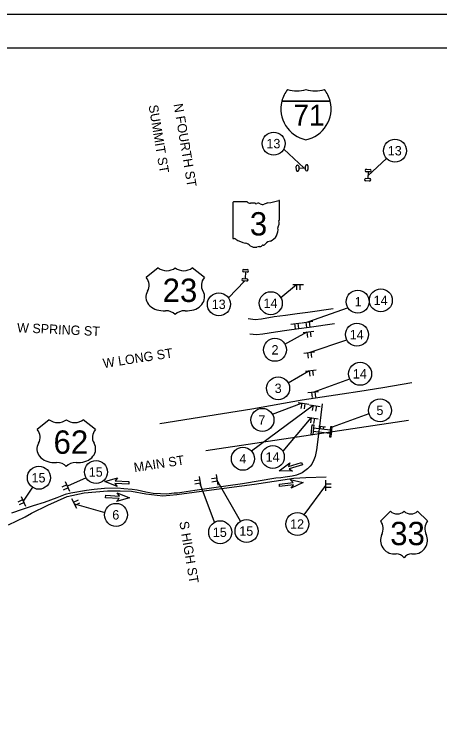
# Model space of a CAD drawing. Extents: x 0 to 680, y 0 to 440.
# Drawn here: x 417.5 to 544.5, y 225.4 to 440 of the extents above; entities that cross this region are included whole.
import ezdxf

# ---------------------------------------------------------------- set-up
doc = ezdxf.new("R2010")
doc.units = 0
for name, color, linetype in [('GM_X_Corporation_Text', 7, 'Continuous'), ('GM_X_County', 7, 'Continuous'), ('GM_X_County_Road_Text', 7, 'Continuous'), ('GM_X_Major_Lake', 7, 'Continuous'), ('GM_X_Major_River', 7, 'Continuous'), ('GM_X_Minor_Lake', 7, 'Continuous'), ('GM_X_Minor_River', 7, 'Continuous'), ('GM_X_Minor_River_Text', 7, 'Continuous'), ('GM_X_State_Location', 7, 'Continuous'), ('GM_X_Township_Text', 7, 'Continuous'), ('GM_X_Unincorporated_Location', 7, 'Continuous'), ('GM_X_Unincorporated_Text', 7, 'Continuous')]:
    doc.layers.add(name, color=color, linetype=linetype)

msp = doc.modelspace()

# ---------------------------------------------------------------- linework, layer by layer
at = {"layer": 'GM_X_Corporation_Text'}
for points in [[(509.45, 323.78), (508.34, 314.72), (507.7, 310.05), (507.29, 308.14), (506.94, 307.16), (506.33, 305.84), (505.8, 305.18), (505.05, 304.44), (503.41, 303.27), (501.78, 302.54), (500.42, 302.21), (498.4, 301.94), (497.08, 301.76), (495.57, 301.68), (485.62, 299.99), (476.34, 298.7), (471.42, 297.99), (466.21, 297.17), (465.2, 297.13), (462.96, 296.9), (461.12, 296.94), (458.95, 297.06), (456.78, 297.51), (454.16, 298.02), (452.7, 298.26), (450.19, 298.49), (448.34, 298.63), (444.42, 298.55), (441.36, 298.28), (439.1, 298), (434.38, 297.16), (432.71, 296.73), (430.18, 295.75), (426.46, 294.42), (423.12, 293.36), (419.85, 292.29), (416.65, 291.16)], [(415.79, 287.72), (420.78, 290.12), (422.67, 291.23), (427.47, 293.62), (433.31, 296.13), (438.41, 297.23), (445.33, 297.83), (449.12, 297.83), (452.53, 297.77), (456.75, 297.01), (461.88, 296.36), (466, 296.81), (476.41, 298.21), (489.2, 299.87), (500.99, 301.61), (504.58, 301.84), (510.59, 302.02)]]:
    msp.add_lwpolyline(points, dxfattribs=at)
at = {"layer": 'GM_X_County'}
msp.add_lwpolyline([(0, 0), (680, 0), (680, 440), (0, 440)], close=True, dxfattribs=at)
at = {"layer": 'GM_X_County_Road_Text'}
for p, q in [((460.49, 364.36), (456.86, 361.46)), ((474.27, 361.46), (470.64, 364.36)), ((461.94, 351.6), (462.66, 351.6)), ((468.47, 351.6), (469.19, 351.6)), ((427.96, 319.07), (424.33, 316.17)), ((441.73, 316.17), (438.11, 319.07)), ((429.41, 306.31), (430.13, 306.31)), ((435.93, 306.31), (436.66, 306.31)), ((529.8, 291.8), (526.9, 288.9)), ((540.82, 288.9), (537.92, 291.8)), ((530.96, 279.04), (531.54, 279.04)), ((536.18, 279.04), (536.76, 279.04))]:
    msp.add_line(p, q, dxfattribs=at)
for centre, radius, start, end in [((531.83, 293.87), 2.9, 225.573, 314.427), ((535.89, 293.87), 2.9, 225.573, 314.427), ((523.57, 286.57), 4.06, 334.5471, 35.0009), ((544.15, 286.57), 4.06, 144.9991, 205.4529), ((530.91, 283.1), 4.06, 154.8319, 270.6383), ((536.8, 283.1), 4.06, 269.3617, 25.1681), ((531.54, 276.14), 2.9, 36.8699, 90), ((536.18, 276.14), 2.9, 90, 143.1301)]:
    msp.add_arc(centre, radius, start, end, dxfattribs=at)
for centre, major_axis, start_param, end_param in [((463.03, 366.44), (-3.63, 0), 0.795399, 2.346194), ((468.1, 366.44), (-3.63, 0), 0.795399, 2.346194), ((452.71, 359.13), (5.08, 0), 5.838949, 6.894067), ((478.42, 359.13), (-5.08, 0), 5.672304, 6.727422), ((461.88, 355.66), (5.08, 0), 2.702327, 4.723529), ((469.25, 355.66), (-5.08, 0), 1.559657, 3.580859), ((462.66, 348.7), (-3.63, 0), 3.785094, 4.712389), ((468.47, 348.7), (-3.63, 0), 4.712389, 5.639684), ((430.5, 321.14), (-3.63, 0), 0.795399, 2.346194), ((435.57, 321.14), (-3.63, 0), 0.795399, 2.346194), ((420.17, 313.84), (5.08, 0), 5.838949, 6.894067), ((445.89, 313.84), (-5.08, 0), 5.672304, 6.727422), ((429.35, 310.37), (5.08, 0), 2.702327, 4.723529), ((436.72, 310.37), (-5.08, 0), 1.559657, 3.580859), ((430.13, 303.41), (-3.63, 0), 3.785094, 4.712389), ((435.93, 303.41), (-3.63, 0), 4.712389, 5.639684)]:
    msp.add_ellipse(centre, major_axis=major_axis, ratio=0.8, start_param=start_param, end_param=end_param, dxfattribs=at)
at = {"layer": 'GM_X_Major_Lake'}
for p, q in [((511.7, 315), (506.73, 315.55)), ((511.81, 315.99), (506.84, 316.55)), ((508.42, 317.13), (510.4, 316.91)), ((508.83, 316.33), (508.91, 317.07)), ((509.27, 315.77), (509.27, 315.77)), ((509.82, 316.22), (509.91, 316.96)), ((496.57, 303.87), (499.79, 306.2)), ((499.34, 305.1), (503.29, 306.29)), ((499.79, 306.2), (499.34, 305.1)), ((503.51, 305.57), (499.56, 304.38)), ((503.29, 306.29), (503.51, 305.57)), ((503.4, 305.93), (503.4, 305.93)), ((496.57, 303.87), (496.57, 303.87)), ((500.54, 303.71), (496.57, 303.87)), ((499.56, 304.38), (500.54, 303.71)), ((444.56, 300.6), (448.36, 301.72)), ((444.56, 300.6), (444.56, 300.6)), ((448.24, 299.12), (444.56, 300.6)), ((448.36, 301.72), (447.57, 300.83)), ((447.57, 300.83), (451.69, 300.64)), ((451.69, 300.64), (451.66, 299.89)), ((500.74, 300.36), (499.89, 301.2)), ((499.89, 301.2), (503.76, 300.33)), ((451.66, 299.89), (447.54, 300.08)), ((447.54, 300.08), (448.24, 299.12)), ((451.67, 300.26), (451.67, 300.26)), ((496.64, 299.9), (500.74, 300.36)), ((496.72, 299.15), (496.64, 299.9)), ((496.68, 299.52), (496.68, 299.52)), ((500.82, 299.62), (496.72, 299.15)), ((503.76, 300.33), (500.18, 298.61)), ((500.18, 298.61), (500.82, 299.62)), ((503.76, 300.33), (503.76, 300.33)), ((444.74, 295.79), (444.79, 296.54)), ((444.76, 296.17), (444.76, 296.17)), ((444.79, 296.54), (448.9, 296.31)), ((448.9, 296.31), (448.21, 297.28)), ((448.21, 297.28), (451.88, 295.77)), ((448.86, 295.56), (444.74, 295.79)), ((451.88, 295.77), (448.06, 294.68)), ((448.06, 294.68), (448.86, 295.56)), ((451.88, 295.77), (451.88, 295.77))]:
    msp.add_line(p, q, dxfattribs=at)
for points in [[(506.12, 314.62), (506.46, 317.6), (506.95, 317.54), (506.62, 314.56)], [(512.09, 313.95), (512.42, 316.93), (511.92, 316.99), (511.59, 314.01)]]:
    msp.add_lwpolyline(points, close=True, dxfattribs=at)
at = {"layer": 'GM_X_Major_River'}
for p, q in [((497.38, 414.1), (511.8, 414.1)), ((511.8, 414.1), (497.38, 414.1)), ((511.8, 414.1), (497.38, 414.1))]:
    msp.add_line(p, q, dxfattribs=at)
for centre, start, end in [((506.46, 411.8), 141.669, 165.8066), ((501.85, 426.58), 253.0091, 286.9909), ((507.33, 426.58), 253.0091, 286.9909), ((502.71, 411.8), 14.1934, 38.331), ((506.46, 411.8), 165.8066, 258.463), ((502.71, 411.8), 281.537, 14.1934)]:
    msp.add_arc(centre, 9.38, start, end, dxfattribs=at)
at = {"layer": 'GM_X_Minor_Lake'}
for p, q in [((497.95, 399.8), (503.9, 394.19)), ((523.07, 391.82), (528.61, 397.05)), ((481.42, 355.46), (486.27, 360.45)), ((497.08, 355.51), (501.75, 359.42)), ((517.15, 352.42), (505.02, 348.23)), ((498.27, 341.65), (504.96, 345.29)), ((505.55, 339.14), (516.78, 342.93)), ((499.25, 330.07), (505.4, 333.67)), ((506.75, 327.34), (517.67, 331.28)), ((494.62, 320.7), (503.22, 324.06)), ((488.28, 309.75), (506.73, 323.37)), ((512.5, 316.97), (523.41, 320.92)), ((497.73, 309.65), (506.16, 319.69)), ((438.94, 301.77), (433.34, 299.21)), ((485.06, 288.79), (478.01, 301.18)), ((422.93, 298.92), (420.2, 294.77)), ((477.31, 288.52), (473.04, 299.93)), ((504.07, 290.72), (510.51, 299.44)), ((435.43, 293.98), (444.55, 291.42))]:
    msp.add_line(p, q, dxfattribs=at)
for centre in [(494.94, 401.45), (531.16, 399.33), (478.59, 353.51), (494.08, 353.84), (520.03, 354.28), (526.93, 354.68), (519.8, 344.47), (495.33, 339.93), (520.74, 332.77), (496.27, 328.45), (526.69, 321.87), (491.58, 319.03), (494.69, 307.97), (485.75, 307.43), (441.92, 303.48), (424.85, 301.77), (447.88, 290.7), (502.01, 287.95), (478.97, 285.51), (486.85, 285.86)]:
    msp.add_circle(centre, 3.43, dxfattribs=at)
at = {"layer": 'GM_X_Minor_River_Text'}
msp.add_lwpolyline([(30, 430), (670, 430), (670, 10), (30, 10)], close=True, dxfattribs=at)
at = {"layer": 'GM_X_State_Location'}
msp.add_line((474.72, 309.85), (535.21, 318.98), dxfattribs=at)
at = {"layer": 'GM_X_Township_Text'}
for points in [[(512.66, 352.18), (505.13, 351.04), (501.98, 350.66), (498.46, 350.16), (495.04, 349.73), (491.27, 349.12), (489.38, 348.87), (487.37, 349.14)], [(513.09, 347.68), (505.56, 346.55), (502.41, 346.16), (498.89, 345.66), (495.46, 345.24), (491.7, 344.62), (489.8, 344.37), (487.8, 344.64)], [(536.19, 330.12), (527.57, 328.57), (520.64, 327.5), (515.41, 326.66), (503.46, 324.96), (488.41, 322.27), (475.33, 320.15), (460.98, 317.84)]]:
    msp.add_lwpolyline(points, dxfattribs=at)
at = {"layer": 'GM_X_Unincorporated_Location'}
for p, q in [((496.69, 378.78), (496.69, 384.3)), ((482.77, 383.86), (482.77, 373.29)), ((486.99, 384.04), (482.91, 384.04)), ((496.69, 378.78), (496.69, 378.78))]:
    msp.add_line(p, q, dxfattribs=at)
for centre, radius, start, end in [((491.73, 398.45), 14.76, 275.8445, 288.9065), ((496.54, 384.33), 0.155, 351.8621, 97.738), ((482.93, 383.88), 0.161, 98.1301, 188.1301), ((487.96, 385.27), 1.56, 231.6195, 271.1119), ((488.48, 378.11), 5.62, 80.4867, 94.9883), ((489.75, 383.94), 0.451, 219.7921, 297.1024), ((490.41, 382.72), 0.938, 54.4667, 119.1411), ((491.62, 384.39), 1.13, 233.8562, 294.8282), ((493.62, 380.81), 2.97, 97.3462, 120.7689), ((496.66, 378.37), 0.24, 107.944, 210.337), ((495.13, 377.67), 1.44, 340.033, 23.6496), ((496.53, 378.75), 0.166, 289.6038, 7.7341), ((492.56, 375.76), 3.69, 292.3089, 8.9858), ((497.25, 376.46), 1.05, 136.8065, 186.9296), ((482.93, 373.27), 0.163, 171.9584, 258.3066), ((482.96, 374.35), 1.24, 267.339, 280.6039), ((483.21, 372.68), 0.448, 29.7484, 93.2717), ((488.86, 382.18), 10.66, 240.4129, 257.1985), ((485.69, 368.55), 3.34, 47.1842, 75.836), ((491.56, 372.27), 1.19, 282.8732, 323.2771), ((494.12, 370.33), 2.02, 94.4031, 142.5768), ((489.29, 372.63), 2.12, 230.7004, 286.2918), ((490.52, 368.98), 1.74, 85.6951, 111.2099), ((490.67, 371.84), 1.13, 268.777, 315.5493), ((491.69, 370.82), 0.318, 65.7517, 132.6484)]:
    msp.add_arc(centre, radius, start, end, dxfattribs=at)
at = {"layer": 'GM_X_Unincorporated_Text'}
for p, q in [((501.74, 393.51), (501.7, 394.6)), ((502.45, 394.12), (504.43, 394.21)), ((504.45, 393.67), (504.41, 394.76)), ((522.62, 393.8), (523.7, 393.72)), ((523.15, 393.03), (523.01, 391.05)), ((522.47, 391.09), (523.56, 391.01)), ((485.98, 363.93), (487.07, 363.85)), ((486.51, 363.15), (486.38, 361.18)), ((485.83, 361.22), (486.92, 361.14)), ((500.64, 359.41), (503.84, 359.46)), ((501.76, 359.42), (501.79, 357.82)), ((502.24, 359.43), (502.24, 359.43)), ((502.72, 359.44), (502.75, 357.84)), ((500.08, 347.6), (503.25, 348.01)), ((501.19, 347.74), (501.4, 346.16)), ((501.67, 347.8), (501.67, 347.8)), ((502.14, 347.87), (502.35, 346.28)), ((503.43, 348.03), (506.6, 348.44)), ((504.54, 348.17), (504.75, 346.58)), ((505.02, 348.23), (505.02, 348.23)), ((505.49, 348.29), (505.7, 346.71)), ((503.74, 345.09), (506.92, 345.5)), ((504.85, 345.23), (505.06, 343.65)), ((505.33, 345.3), (505.33, 345.3)), ((505.81, 345.36), (506.01, 343.77)), ((503.96, 338.95), (507.14, 339.33)), ((505.08, 339.08), (505.27, 337.49)), ((505.55, 339.14), (505.55, 339.14)), ((506.03, 339.2), (506.22, 337.61)), ((504.46, 333.55), (507.63, 333.96)), ((505.57, 333.69), (505.77, 332.1)), ((506.04, 333.75), (506.04, 333.75)), ((506.52, 333.81), (506.72, 332.23)), ((505.17, 327.15), (508.34, 327.53)), ((506.28, 327.28), (506.47, 325.69)), ((506.75, 327.34), (506.75, 327.34)), ((507.23, 327.4), (507.42, 325.81)), ((502.23, 324.22), (505.39, 323.7)), ((503.33, 324.04), (503.07, 322.46)), ((503.81, 323.96), (503.81, 323.96)), ((504.28, 323.88), (504.02, 322.31)), ((505.62, 323.55), (508.78, 323.03)), ((506.73, 323.37), (506.47, 321.79)), ((507.2, 323.29), (507.2, 323.29)), ((507.68, 323.21), (507.41, 321.64)), ((505.06, 319.88), (508.22, 319.35)), ((506.16, 319.69), (505.9, 318.12)), ((506.64, 319.62), (506.64, 319.62)), ((507.11, 319.54), (506.85, 317.96)), ((477.76, 302.77), (478.25, 299.6)), ((432.65, 300.66), (434.03, 297.77)), ((472.87, 301.06), (471.29, 300.82)), ((472.7, 302.17), (473.18, 299.01)), ((472.94, 300.59), (472.94, 300.59)), ((477.94, 301.66), (476.35, 301.42)), ((478.08, 300.71), (476.5, 300.47)), ((478.01, 301.18), (478.01, 301.18)), ((510.54, 297.84), (510.47, 301.04)), ((433.14, 299.65), (431.69, 298.96)), ((433.55, 298.78), (432.11, 298.09)), ((433.34, 299.21), (433.34, 299.21)), ((473.01, 300.11), (471.43, 299.87)), ((510.5, 299.92), (512.1, 299.96)), ((510.51, 299.44), (510.51, 299.44)), ((510.52, 298.96), (512.12, 299)), ((419.51, 296.22), (420.89, 293.33)), ((419.99, 295.21), (418.55, 294.52)), ((420.41, 294.34), (418.96, 293.65)), ((420.2, 294.77), (420.2, 294.77)), ((436.13, 292.59), (434.72, 295.47)), ((435.21, 294.46), (436.65, 295.17)), ((435.42, 294.03), (435.42, 294.03)), ((435.63, 293.6), (437.07, 294.3))]:
    msp.add_line(p, q, dxfattribs=at)
for points in [[(505.14, 394.83), (505.18, 393.74)], [(502.43, 394.67), (502.47, 393.58)], [(523.69, 392.99), (522.61, 393.07)], [(523.54, 390.28), (522.46, 390.36)], [(487.06, 363.11), (485.97, 363.19)], [(486.91, 360.4), (485.82, 360.48)]]:
    msp.add_lwpolyline(points, dxfattribs=at)
for centre, start, end in [((502.07, 394.63), 6.2805, 184.6343), ((504.78, 394.79), 6.2805, 184.6343), ((502.11, 393.55), 186.2805, 4.6343), ((504.82, 393.71), 186.2805, 4.6343), ((522.62, 393.43), 89.8181, 268.1719), ((523.69, 393.35), 269.8181, 88.1719), ((522.47, 390.72), 89.8181, 268.1719), ((523.54, 390.64), 269.8181, 88.1719), ((485.98, 363.56), 89.8181, 268.1719), ((487.06, 363.48), 269.8181, 88.1719), ((485.83, 360.85), 89.8181, 268.1719), ((486.91, 360.77), 269.8181, 88.1719)]:
    msp.add_arc(centre, 0.367, start, end, dxfattribs=at)

# ---------------------------------------------------------------- texts
at = {"layer": 'GM_X_County_Road_Text'}
for s, p in [('23', (461.78, 354.21)), ('62', (429.22, 308.92)), ('33', (529.73, 281.65))]:
    msp.add_text(s, height=6.961, dxfattribs=at).set_placement(p)
at = {"layer": 'GM_X_Major_River'}
msp.add_text('71', height=6.25, dxfattribs=at).set_placement((500.83, 406.84))
at = {"layer": 'GM_X_Minor_Lake'}
for s, rotation, p in [('SUMMIT ST', 279.5121, (457.58, 412.79)), ('N FOURTH ST', 279.5121, (465.05, 413.17)), ('W SPRING ST', 357.3382, (418.28, 345.18)), ('W LONG ST', 8.7669, (444.19, 334.48)), ('MAIN ST', 8.7669, (453.41, 303.42)), ('S HIGH ST', 279.5121, (466.76, 288.56))]:
    msp.add_text(s, height=2.8, rotation=rotation, dxfattribs=at).set_placement(p)
for s, p in [('13', (492.78, 400.05)), ('13', (529.01, 397.93)), ('13', (476.44, 352.11)), ('14', (491.92, 352.44)), ('1', (519.12, 352.88)), ('14', (524.78, 353.28)), ('14', (517.65, 343.07)), ('2', (494.29, 338.53)), ('14', (518.58, 331.37)), ('3', (495.23, 327.05)), ('5', (525.62, 320.47)), ('7', (490.39, 317.63)), ('14', (492.53, 306.57)), ('4', (484.71, 306.03)), ('15', (439.73, 302.08)), ('15', (422.66, 300.37)), ('6', (446.76, 289.3)), ('12', (499.85, 286.55)), ('15', (476.78, 284.11)), ('15', (484.67, 284.46))]:
    msp.add_text(s, height=2.8, dxfattribs=at).set_placement(p)
at = {"layer": 'GM_X_Minor_River'}
for s in ['0', '/']:
    msp.add_text(s, height=0.01, dxfattribs=at).set_placement((532.58, 262.38))
msp.add_text('33', height=0.01, rotation=0, dxfattribs=at).set_placement((530.51, 260.31))
at = {"layer": 'GM_X_Unincorporated_Location'}
msp.add_text('3', height=6.96, dxfattribs=at).set_placement((487.83, 374.04))

doc.saveas('drawing.dxf')
